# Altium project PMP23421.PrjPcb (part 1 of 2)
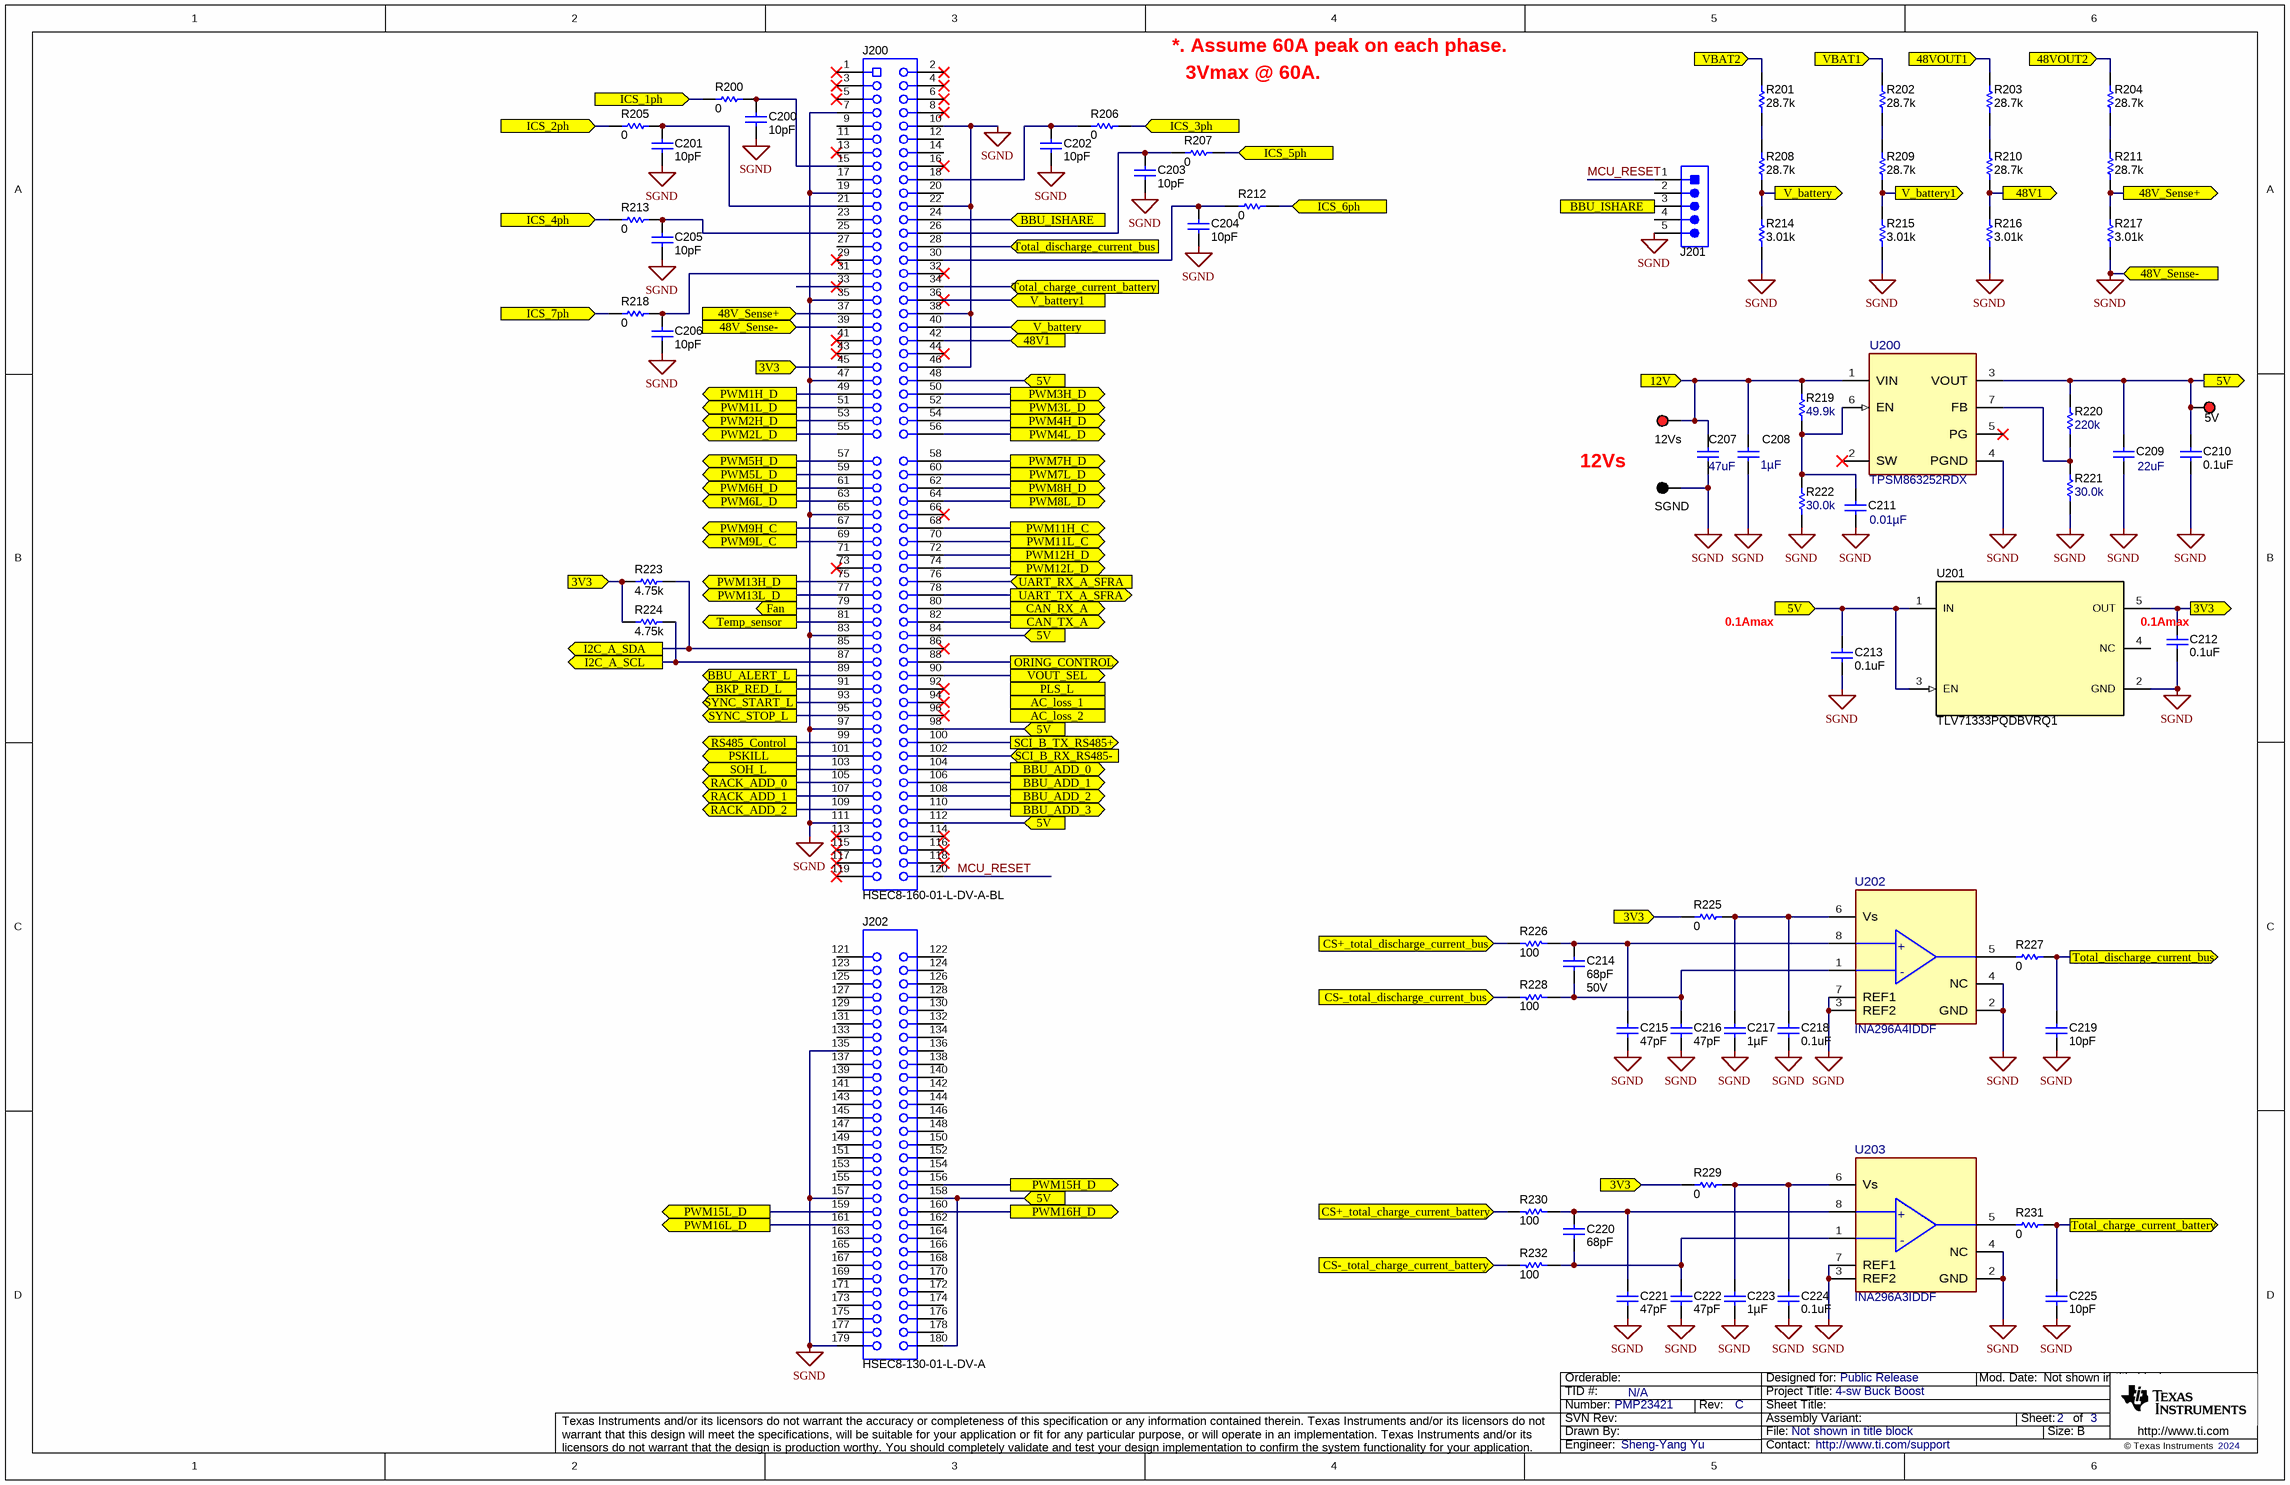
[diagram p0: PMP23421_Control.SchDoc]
CopyrightYear: 2024; PCB_Layout: Sheng-Yang Yu; PCB_Rev: C; PRJ_Customer: Public Release; PRJ_Engineer: Sheng-Yang Yu; PRJ_Number: PMP23421; PRJ_Title: 4-sw Buck Boost; SCH_Rev: C; TechSupport: http://www.ti.com/support; TID: N/A
3 sheets, 215 parts. Net scope: flat (ports and power ports of the same name join across sheets).
Board file: PMP23421.PcbDoc
Sheets:
  PMP23421_Control.SchDoc
  PMP23421_ORING_N_CS.SchDoc
  PMP23421_buffer.SchDoc

## Sheet PMP23421_Control.SchDoc
size 431 x 279 mm; Date: Not shown in title block; ApprovedBy: Not shown in title block; CheckedBy: Not shown in title block; Author: Not shown in title block; CompanyName: Not shown in title block; Engineer: Not shown in title block; Organization: Not shown in title block; Address1: Not shown in title block; Address2: Not shown in title block; Address3: Not shown in title block; Address4: Not shown in title block; DocumentNumber: 2; Revision: Use project parameter SCH_Rev; SheetNumber: 2; SheetTotal: 3; PageSetup: Record=PageOptions¦CenterHorizontal=True¦CenterVertical=True¦PrintScale=1.00¦XCorrection=1.00¦YCorrection=1.00¦PrintKind=0¦BorderSize=5000000¦LeftOffset=0¦BottomOffset=0¦Orientation=2¦PaperLength=1000¦PaperWidth=1000¦Scale=100¦PaperSource=15¦PrintQuality=600¦MediaType=1¦DitherType=10¦PaperKind=Letter¦PrintScaleMode=1

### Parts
5V  5000  [Keystone5000]  (value not drawn)
12Vs  5000  [Keystone5000]  (value not drawn)
C200  ValueDisplayed: 10pF  [0603]  (hidden comment: C0603C100F5GAC7867)
C201  ValueDisplayed: 10pF  [0603]  (hidden comment: C0603C100F5GAC7867)
C202  ValueDisplayed: 10pF  [0603]  (hidden comment: C0603C100F5GAC7867)
C203  ValueDisplayed: 10pF  [0603]  (hidden comment: C0603C100F5GAC7867)
C204  ValueDisplayed: 10pF  [0603]  (hidden comment: C0603C100F5GAC7867)
C205  ValueDisplayed: 10pF  [0603]  (hidden comment: C0603C100F5GAC7867)
C206  ValueDisplayed: 10pF  [0603]  (hidden comment: C0603C100F5GAC7867)
C207  ValueDisplayed: 47uF  [1210_270]  (hidden comment: GRM32ER61C476KE15L)
C208  Cap_F: 1µF  [0805_HV]  (hidden comment: C0805C105K3RACTU)
C209  ValueDisplayed: 22uF  [0805_HV]  (hidden comment: CL21A226KQQNNNE)
C210  ValueDisplayed: 0.1uF  [0402]  (hidden comment: GRM155R70J104KA01D)
C211  ValueDisplayed: 0.01µF  [0402]  (hidden comment: C0402C103K4RACTU)
C212  ValueDisplayed: 0.1uF  [0402]  (hidden comment: GRM155R70J104KA01D)
C213  ValueDisplayed: 0.1uF  [0402]  (hidden comment: GRM155R70J104KA01D)
C214  ValueDisplayed: 68pF  Value2: 50V  [0603]  (hidden comment: 06035A680JAT2A)
C215  ValueDisplayed: 47pF  [0402]  (hidden comment: GRM1555C1H470FA01D)
C216  ValueDisplayed: 47pF  [0402]  (hidden comment: GRM1555C1H470FA01D)
C217  ValueDisplayed: 1µF  [0603]  (hidden comment: C1608X7R1C105K080AC)
C218  ValueDisplayed: 0.1uF  [0402]  (hidden comment: GRM155R70J104KA01D)
C219  ValueDisplayed: 10pF  [0603]  (hidden comment: C0603C100F5GAC7867)
C220  ValueDisplayed: 68pF  [0603]  (hidden comment: 06035A680JAT2A)
C221  ValueDisplayed: 47pF  [0402]  (hidden comment: GRM1555C1H470FA01D)
C222  ValueDisplayed: 47pF  [0402]  (hidden comment: GRM1555C1H470FA01D)
C223  ValueDisplayed: 1µF  [0603]  (hidden comment: C1608X7R1C105K080AC)
C224  ValueDisplayed: 0.1uF  [0402]  (hidden comment: GRM155R70J104KA01D)
C225  ValueDisplayed: 10pF  [0603]  (hidden comment: C0603C100F5GAC7867)
J200  HSEC8-160-01-L-DV-A-BL  [controlCARD-120HSEC]
J201  61300511021  [Wurth_61300511021]  (value not drawn)
J202  HSEC8-130-01-L-DV-A  [controlCARD-180HSEC-60pinAddon]
R200  ValueDisplayed: 0  [0603]  (hidden comment: RC0603JR-070RL)
R201  ValueDisplayed: 28.7k  [0603]  (hidden comment: CRCW060328K7FKEA)
R202  ValueDisplayed: 28.7k  [0603]  (hidden comment: CRCW060328K7FKEA)
R203  ValueDisplayed: 28.7k  [0603]  (hidden comment: CRCW060328K7FKEA)
R204  ValueDisplayed: 28.7k  [0603]  (hidden comment: CRCW060328K7FKEA)
R205  ValueDisplayed: 0  [0603]  (hidden comment: RC0603JR-070RL)
R206  ValueDisplayed: 0  [0603]  (hidden comment: RC0603JR-070RL)
R207  ValueDisplayed: 0  [0603]  (hidden comment: RC0603JR-070RL)
R208  ValueDisplayed: 28.7k  [0603]  (hidden comment: CRCW060328K7FKEA)
R209  ValueDisplayed: 28.7k  [0603]  (hidden comment: CRCW060328K7FKEA)
R210  ValueDisplayed: 28.7k  [0603]  (hidden comment: CRCW060328K7FKEA)
R211  ValueDisplayed: 28.7k  [0603]  (hidden comment: CRCW060328K7FKEA)
R212  ValueDisplayed: 0  [0603]  (hidden comment: RC0603JR-070RL)
R213  ValueDisplayed: 0  [0603]  (hidden comment: RC0603JR-070RL)
R214  ValueDisplayed: 3.01k  [0603]  (hidden comment: CRCW06033K01FKEA)
R215  ValueDisplayed: 3.01k  [0603]  (hidden comment: CRCW06033K01FKEA)
R216  ValueDisplayed: 3.01k  [0603]  (hidden comment: CRCW06033K01FKEA)
R217  ValueDisplayed: 3.01k  [0603]  (hidden comment: CRCW06033K01FKEA)
R218  ValueDisplayed: 0  [0603]  (hidden comment: RC0603JR-070RL)
R219  ValueDisplayed: 49.9k  [0402]  (hidden comment: CRCW040249K9FKED)
R220  ValueDisplayed: 220k  [0402]  (hidden comment: RC0402FR-07220KL)
R221  ValueDisplayed: 30.0k  [0402]  (hidden comment: CRCW040230K0FKED)
R222  ValueDisplayed: 30.0k  [0402]  (hidden comment: CRCW040230K0FKED)
R223  ValueDisplayed: 4.75k  [0603]  (hidden comment: CRCW06034K75FKEA)
R224  ValueDisplayed: 4.75k  [0603]  (hidden comment: CRCW06034K75FKEA)
R225  ValueDisplayed: 0  [0603]  (hidden comment: RC0603JR-070RL)
R226  ValueDisplayed: 100  [0603]  (hidden comment: RC0603FR-07100RL)
R227  ValueDisplayed: 0  [0603]  (hidden comment: RC0603JR-070RL)
R228  ValueDisplayed: 100  [0603]  (hidden comment: RC0603FR-07100RL)
R229  ValueDisplayed: 0  [0603]  (hidden comment: RC0603JR-070RL)
R230  ValueDisplayed: 100  [0603]  (hidden comment: RC0603FR-07100RL)
R231  ValueDisplayed: 0  [0603]  (hidden comment: RC0603JR-070RL)
R232  ValueDisplayed: 100  [0603]  (hidden comment: RC0603FR-07100RL)
SGND  5001  [Keystone5001]  (value not drawn)
U200  TPSM863252RDX  [RDX0007A-MFG]
U201  TLV71333PQDBVRQ1  [DBV0005A_N]
U202  INA296A4IDDF  [DDF0008A-MFG]
U203  INA296A3IDDF  [DDF0008A-MFG]

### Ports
3V3 (in), 3V3 (out), 5V (in), 5V (out), 12V (in), 48V1 (in), 48V1 (out), 48V_Sense+ (in), 48V_Sense+ (out), 48V_Sense- (in), 48VOUT1 (in), 48VOUT2 (in), AC_loss_1 (out), AC_loss_2 (out), BBU_ADD_0 (out), BBU_ADD_1 (out), BBU_ADD_2 (out), BBU_ADD_3 (out), BBU_ALERT_L (out), BBU_ISHARE (in), BKP_RED_L (out), CAN_RX_A (out), CAN_TX_A (out), CS+_total_charge_current_battery (in), CS+_total_discharge_current_bus (in), CS-_total_charge_current_battery (in), CS-_total_discharge_current_bus (in), Fan (out), I2C_A_SCL (out), I2C_A_SDA (out), ICS_1ph (in), ICS_2ph (in), ICS_3ph (in), ICS_4ph (in), ICS_5ph (in), ICS_6ph (in), ICS_7ph (in), ORING_CONTROL (out), PLS_L (out), PSKILL (out), PWM1H_D (out), PWM1L_D (out), PWM2H_D (out), PWM2L_D (out), PWM3H_D (out), PWM3L_D (out), PWM4H_D (out), PWM4L_D (out), PWM5H_D (out), PWM5L_D (out), PWM6H_D (out), PWM6L_D (out), PWM7H_D (out), PWM7L_D (out), PWM8H_D (out), PWM8L_D (out), PWM9H_C (out), PWM9L_C (out), PWM11H_C (out), PWM11L_C (out), PWM12H_D (out), PWM12L_D (out), PWM13H_D (out), PWM13L_D (out), PWM15H_D (out), PWM15L_D (out), PWM16H_D (out), PWM16L_D (out), RACK_ADD_0 (out), RACK_ADD_1 (out), RACK_ADD_2 (out), RS485_Control (out), SCI_B_RX_RS485- (in), SCI_B_TX_RS485+ (out), SOH_L (out), SYNC_START_L (out), SYNC_STOP_L (out), Temp_sensor (out), Total_charge_current_battery (in), Total_charge_current_battery (out), Total_discharge_current_bus (in), Total_discharge_current_bus (out), UART_RX_A_SFRA (in), UART_TX_A_SFRA (out), V_battery1 (in), V_battery1 (out), V_battery (in), V_battery (out), VBAT1 (in), VBAT2 (in), VOUT_SEL (out)

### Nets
SGND: C200.2 C201.2 C202.2 C203.2 C204.2 C205.2 C206.2 C207.2 C208.2 C209.2 C210.2 C211.2 C212.2 C213.2 C215.2 C216.2 C217.2 C218.2 C219.2 C221.2 C222.2 C223.2 C224.2 C225.2 J200.7 J200.10 J200.19 J200.22 J200.35 J200.38 J200.39 J200.46 J200.47 J200.65 J200.83 J200.97 J200.111 J201.5 J202.135 J202.157 J202.179 R214.1 R215.1 R216.1 R217.1 R221.1 R222.1 SGND.1 U200.4(PGND) U201.2(GND) U202.2(GND) U202.3(REF2) U202.4(NC) U202.7(REF1) U203.2(GND) U203.3(REF2) U203.4(NC) U203.7(REF1) ; port 48V_Sense-
3V3: C212.1 J200.45 R223.2 R224.2 R225.1 R229.1 U201.5(OUT) ; port 3V3
5V: 5V.1 C209.1 C210.1 C213.1 J200.48 J200.84 J200.98 J200.112 J202.158 J202.180 R220.2 U200.3(VOUT) U201.1(IN) U201.3(EN) ; port 5V
12V: 12Vs.1 C207.1 C208.1 R219.2 U200.1(VIN) ; port 12V
48V1: J200.42 R210.1 R216.2 ; port 48V1
48V_Sense+: J200.37 R211.1 R217.2 ; port 48V_Sense+
48VOUT1: R203.2 R226.2 ; port 48VOUT1, port CS+_total_discharge_current_bus
48VOUT2: R204.2 ; port 48VOUT2
BBU_ADD_0: J200.104 ; port BBU_ADD_0
BBU_ADD_1: J200.106 ; port BBU_ADD_1
BBU_ADD_2: J200.108 ; port BBU_ADD_2
BBU_ADD_3: J200.110 ; port BBU_ADD_3
BBU_ALERT_L: J200.89 ; port BBU_ALERT_L
BBU_ISHARE: J200.24 J201.3 ; port BBU_ISHARE
BKP_RED_L: J200.91 ; port BKP_RED_L
CAN_RX_A: J200.80 ; port CAN_RX_A
CAN_TX_A: J200.82 ; port CAN_TX_A
CS+_total_charge_current_battery: R202.2 R230.2 ; port VBAT1, port CS+_total_charge_current_battery
CS-_total_charge_current_battery: R201.2 R232.2 ; port VBAT2, port CS-_total_charge_current_battery
CS-_total_discharge_current_bus: R228.2 ; port CS-_total_discharge_current_bus
Fan: J200.79 ; port Fan
I2C_A_SCL: J200.87 R224.1 ; port I2C_A_SCL
I2C_A_SDA: J200.85 R223.1 ; port I2C_A_SDA
ICS_1ph: R200.1 ; port ICS_1ph
ICS_2ph: R205.1 ; port ICS_2ph
ICS_3ph: R206.2 ; port ICS_3ph
ICS_4ph: R213.1 ; port ICS_4ph
ICS_5ph: R207.2 ; port ICS_5ph
ICS_6ph: R212.2 ; port ICS_6ph
ICS_7ph: R218.1 ; port ICS_7ph
MCU_RESET: J200.120 J201.1
ORING_CONTROL: J200.88 ; port ORING_CONTROL
PSKILL: J200.101 ; port PSKILL
PWM1H_D: J200.49 ; port PWM1H_D
PWM1L_D: J200.51 ; port PWM1L_D
PWM2H_D: J200.53 ; port PWM2H_D
PWM2L_D: J200.55 ; port PWM2L_D
PWM3H_D: J200.50 ; port PWM3H_D
PWM3L_D: J200.52 ; port PWM3L_D
PWM4H_D: J200.54 ; port PWM4H_D
PWM4L_D: J200.56 ; port PWM4L_D
PWM5H_D: J200.57 ; port PWM5H_D
PWM5L_D: J200.59 ; port PWM5L_D
PWM6H_D: J200.61 ; port PWM6H_D
PWM6L_D: J200.63 ; port PWM6L_D
PWM7H_D: J200.58 ; port PWM7H_D
PWM7L_D: J200.60 ; port PWM7L_D
PWM8H_D: J200.62 ; port PWM8H_D
PWM8L_D: J200.64 ; port PWM8L_D
PWM9H_C: J200.67 ; port PWM9H_C
PWM9L_C: J200.69 ; port PWM9L_C
PWM11H_C: J200.68 ; port PWM11H_C
PWM11L_C: J200.70 ; port PWM11L_C
PWM12H_D: J200.72 ; port PWM12H_D
PWM12L_D: J200.74 ; port PWM12L_D
PWM13H_D: J200.75 ; port PWM13H_D
PWM13L_D: J200.77 ; port PWM13L_D
PWM15H_D: J202.156 ; port PWM15H_D
PWM15L_D: J202.159 ; port PWM15L_D
PWM16H_D: J202.160 ; port PWM16H_D
PWM16L_D: J202.161 ; port PWM16L_D
RACK_ADD_0: J200.105 ; port RACK_ADD_0
RACK_ADD_1: J200.107 ; port RACK_ADD_1
RACK_ADD_2: J200.109 ; port RACK_ADD_2
RS485_Control: J200.99 ; port RS485_Control
SCI_B_RX_RS485-: J200.102 ; port SCI_B_RX_RS485-
SCI_B_TX_RS485+: J200.100 ; port SCI_B_TX_RS485+
SOH_L: J200.103 ; port SOH_L
SYNC_START_L: J200.93 ; port SYNC_START_L
SYNC_STOP_L: J200.95 ; port SYNC_STOP_L
Temp_sensor: J200.81 ; port Temp_sensor
Total_charge_current_battery: C225.1 J200.34 R231.2 ; port Total_charge_current_battery
Total_discharge_current_bus: C219.1 J200.28 R227.2 ; port Total_discharge_current_bus
UART_RX_A_SFRA: J200.76 ; port UART_RX_A_SFRA
UART_TX_A_SFRA: J200.78 ; port UART_TX_A_SFRA
V_battery: J200.40 R208.1 R214.2 ; port V_battery
V_battery1: J200.36 R209.1 R215.2 ; port V_battery1
VOUT_SEL: J200.90 ; port VOUT_SEL
NetC200_1: C200.1 J200.15 R200.2
NetC201_1: C201.1 J200.21 R205.2
NetC202_1: C202.1 J200.18 R206.1
NetC203_1: C203.1 J200.26 R207.1
NetC204_1: C204.1 J200.30 R212.1
NetC205_1: C205.1 J200.25 R213.2
NetC206_1: C206.1 J200.31 R218.2
NetC211_1: C211.1 R219.1 R222.2 U200.6(EN)
NetC214_1: C214.1 C215.1 R226.1 U202.8(IN+)
NetC214_2: C214.2 C216.1 R228.1 U202.1(IN-)
NetC217_1: C217.1 C218.1 R225.2 U202.6(Vs)
NetC220_1: C220.1 C221.1 R230.1 U203.8(IN+)
NetC220_2: C220.2 C222.1 R232.1 U203.1(IN-)
NetC223_1: C223.1 C224.1 R229.2 U203.6(Vs)
NetR201_1: R201.1 R208.2
NetR202_1: R202.1 R209.2
NetR203_1: R203.1 R210.2
NetR204_1: R204.1 R211.2
NetR220_1: R220.1 R221.2 U200.7(FB)
NetR227_1: R227.1 U202.5(OUT)
NetR231_1: R231.1 U203.5(OUT)

Not connected (* = marked no-connect by the designer): J200 1* 2* 3* 4* 5* 6* 8* 9 11 12 13* 14 16* 17 20 23 27 29* 32* 33* 41* 43* 44* 66* 71 73* 86* 92* 94* 96* 113* 114* 115* 116* 117* 118* 119*; J201 2 4; J202 121 122 123 124 125 126 127 128 129 130 131 132 133 134 136 137 138 139 140 141 142 143 144 145 146 147 148 149 150 151 152 153 154 155 162 163 164 165 166 167 168 169 170 171 172 173 174 175 176 177 178; U200 2(SW)* 5(PG)*; U201 4(NC)

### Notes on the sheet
- *. Assume 60A peak on each phase.
- 3Vmax @ 60A.
- (near SGND) 12Vs
- (near C213) 0.1Amax
- (near C212) 0.1Amax

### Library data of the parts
5V 12Vs = 5000: Test Point, Miniature, Red, TH; Manufacturer: Keystone; CompType: Test Point Loop; ContactFinish: Silver; Green_Lifecycle: Active; Green_REACh: Passed
C200-C206 C219 C225 = C0603C100F5GAC7867: CAP, CERM, 10 pF, 50 V,+/- 1%, C0G/NP0, 0603; Manufacturer: Kemet; Polarized: N; CompType: Capacitor; Value: 10pF; U/M: EA; Cap_F: 0.00000000001; Tolerance_%: 1; VDC_V: 50; Value2: 50V; TaMin_C: -55; TaMax_C: 125; SizeArea_mm2: 1.28; SizeAreaWB_mm2: 4.68; SizeX_mm: 1.6; SizeY_mm: 0.8; AEC Category: Q200; Green_Lifecycle: Active; Green_REACh: Passed
C207 = CMP-0009211-2: CAP, CERM, 47 uF, 16 V, +/- 10%, X5R, 1210; Manufacturer: MuRata; TaMin_C: -55°C; Polarized: N; SizeAreaWB_mm2: 14.7; Value1: Unknown; U/M: EA; Value: 47uF; TaMax_C: 85°C; SizeZ_mm: 2.7; SizeX_mm: 3.2; SizeY_mm: 2.5; Cap_Case: 1210; Value2: 16V; SizeArea_mm2: 8; CompType: Capacitor; Cap_F: 47µF; AEC Category: Q200
C208 = CMP-0007728-2: CAP, CERM, 1 uF, 25 V, +/- 10%, X7R, 0805; Manufacturer: Kemet; TaMin_C: -55°C; Polarized: N; SizeAreaWB_mm2: 6.75; Value1: Unknown; U/M: EA; Value: 1uF; TaMax_C: 125°C; SizeZ_mm: 1.45; SizeX_mm: 2; SizeY_mm: 1.25; Cap_Case: 0805; Value2: 25V; SizeArea_mm2: 2.5; CompType: Capacitor; AEC Category: Q200
C209 = CMP-0007989-2: CAP, CERM, 22 uF, 6.3 V, +/- 10%, X5R, 0805; Manufacturer: Samsung Electro-Mechanics; TaMin_C: -55°C; Polarized: N; SizeAreaWB_mm2: 6.75; Value1: Unknown; U/M: EA; Value: 22uF; TaMax_C: 85°C; SizeZ_mm: 1.45; SizeX_mm: 2; SizeY_mm: 1.25; Cap_Case: 0805; Value2: 6.3V; SizeArea_mm2: 2.5; CompType: Capacitor; Cap_F: 22µF; AEC Category: Q200
C210 C212 C213 C218 C224 = GRM155R70J104KA01D: CAP, CERM, 0.1uF, 6.3V, +/-10%, X7R, 0402; Manufacturer: MuRata; Polarized: N; CompType: Capacitor; U/M: EA; Cap_F: 0.0000001; Tolerance_%: 10; Value1: Unknown; VDC_V: 6.3; TaMin_C: -55; TaMax_C: 125
C211 = CMP-0078218-1: CAP, CERM, 0.01 µF, 16 V,+/- 10%, X7R, 0402; Manufacturer: Kemet; TaMin_C: -55°C; Polarized: N; Green_Lifecycle: Active; SizeAreaWB_mm2: 3; Green_REACh: Passed; U/M: EA; Value: 0.01uF; TaMax_C: 125°C; SizeZ_mm: 0.6; SizeX_mm: 1; SizeY_mm: 0.5; Value2: 16V; CompType: Capacitor; Cap_F: 10nF; AEC Category: Q200
C214 = 06035A680JAT2A: CAP, CERM, 68 pF, 50 V,+/- 5%, C0G/NP0, 0603; Manufacturer: AVX; Polarized: N; CompType: Capacitor; Value: 68pF; U/M: EA; Cap_F: 0.000000000068; Tolerance_%: 5; ESR_ohm: 0.144; Value1: 0.144 ohm; VDC_V: 50; TaMin_C: -55; TaMax_C: 125; SizeArea_mm2: 1.28; SizeAreaWB_mm2: 4.68; SizeX_mm: 1.6; SizeY_mm: 0.8; SizeZ_mm: 1; AEC Category: Q200; Green_Lifecycle: Active; Green_REACh: Passed
C215 C216 C221 C222 = GRM1555C1H470FA01D: CAP, CERM, 47 pF, 50 V,+/- 1%, C0G/NP0, 0402; Manufacturer: MuRata; Polarized: N; CompType: Capacitor; Value: 47pF; U/M: EA; Cap_F: 0.000000000047; Tolerance_%: 1; VDC_V: 50; Value2: 50V; TaMin_C: -55; TaMax_C: 125; SizeArea_mm2: 0.5; SizeAreaWB_mm2: 3; SizeZ_mm: 0.6; AEC Category: Q200; Green_Lifecycle: Active; Green_REACh: Passed
C217 C223 = C1608X7R1C105K080AC: CAP, CERM, 1 µF, 16 V,+/- 10%, X7R, 0603; Manufacturer: TDK; Polarized: N; CompType: Capacitor; Value: 1uF; U/M: EA; Cap_F: 0.000001; Tolerance_%: 10; ESR_ohm: 0.0057; Value1: 0.0057 ohm; VDC_V: 16; Value2: 16V; TaMin_C: -55; TaMax_C: 125; SizeArea_mm2: 1.28; SizeAreaWB_mm2: 4.68; SizeX_mm: 1.6; SizeY_mm: 0.8; SizeZ_mm: 1; AEC Category: Q200; Green_Lifecycle: Active; Green_REACh: Passed
C220 = 06035A680JAT2A: CAP, CERM, 68 pF, 50 V,+/- 5%, C0G/NP0, 0603; Manufacturer: AVX; Polarized: N; CompType: Capacitor; Value: 68pF; U/M: EA; Cap_F: 0.000000000068; Tolerance_%: 5; ESR_ohm: 0.144; Value1: 0.144 ohm; VDC_V: 50; Value2: 50V; TaMin_C: -55; TaMax_C: 125; SizeArea_mm2: 1.28; SizeAreaWB_mm2: 4.68; SizeX_mm: 1.6; SizeY_mm: 0.8; SizeZ_mm: 1; AEC Category: Q200; Green_Lifecycle: Active; Green_REACh: Passed
J200 = CMP-0003814-2: C2000 controlCARD-120HSEC connector, SMT; Manufacturer: Samtec; Note: The pin numbering does not match Samtec datasheet
J201 = CMP-0054800-1: Header, 2.54 mm, 5x1, Gold, R/A, TH; Manufacturer: Wurth Elektronik; CNHeader: TRUE; Shrouded: N; Gender: Male; Row_Count: 1; Pitch_mm: 2.54; CT: FALSE
J202 = CMP-0003859-2: C2000 controlCARD-180HSEC (60-pin addon) connector, SMT; Manufacturer: Samtec; Note: The pin numbering does not match Samtec datasheet
R200 R205-R207 R212 R213 R218 R225 R227 R229 R231 = RC0603JR-070RL: RES, 0, 5%, 0.1 W, 0603; Manufacturer: Yageo America; CompType: Resistor; Value: 0; Value_Code: 0000; Tolerance_%: 5; Power_W: 0.1; Value2: 0.1W; VDC_V: 50; TempCo: 200 ppm/C; SizeArea_mm2: 1.28; SizeX_mm: 1.6; SizeY_mm: 0.8; SizeZ_mm: 1; EIA_Code: E24; U/M: EA; AEC Category: Q200; Green_Lifecycle: Active; Green_REACh: Passed
R201-R204 R208-R211 = CRCW060328K7FKEA: RES, 28.7 k, 1%, 0.1 W, 0603; Manufacturer: Vishay-Dale; CompType: Resistor; Value: 28.7k; Res_ohm: 28700; Value_Code: 28k7; Tolerance_%: 1; Power_W: 0.1; Value2: 0.1W; VDC_V: 75; TempCo: 100 ppm/C; SizeArea_mm2: 1.28; SizeX_mm: 1.6; SizeY_mm: 0.8; EIA_Code: E96; U/M: EA; AEC Category: Q200
R214-R217 = CRCW06033K01FKEA: RES, 3.01 k, 1%, 0.1 W, 0603; Manufacturer: Vishay-Dale; CompType: Resistor; Value: 3.01k; Res_ohm: 3010; Value_Code: 3k01; Tolerance_%: 1; Power_W: 0.1; Value2: 0.1W; VDC_V: 75; TempCo: 100 ppm/C; SizeArea_mm2: 1.28; SizeX_mm: 1.6; SizeY_mm: 0.8; EIA_Code: E96; U/M: EA; AEC Category: Q200; Green_Lifecycle: Active; Green_REACh: Passed
R219 = CMP-0026403-2: RES, 49.9 k, 1%, 0.063 W, AEC-Q200 Grade 0, 0402; Manufacturer: Vishay-Dale; Power_W: 63mW; TempCo: 100 ppm/C; Value_Code: 49k9; Value: 49.9k; EIA_Code: E96; SizeX_mm: 1; SizeY_mm: 0.5; SizeZ_mm: 0.6; Value2: 0.063W; CompType: Resistor; AEC Qualified: Y; VDC_V: 50V; AEC Category: Q200; AEC Grade: 0
R220 = CMP-0026728-1: RES, 220 k, 1%, 0.0625 W, 0402; Manufacturer: Yageo America; Power_W: 62.5mW; TempCo: 100 ppm/C; U/M: EA; Value: 220k; SizeX_mm: 1; SizeY_mm: 0.5; SizeZ_mm: 0.6; CompType: Resistor; AEC Qualified: N; VDC_V: 50V; AEC Category: Q200
R221 R222 = CMP-0078244-2: RES, 30.0 k, 1%, 0.063 W, AEC-Q200 Grade 0, 0402; Manufacturer: Vishay-Dale; Power_W: 63mW; Green_Lifecycle: Active; TempCo: 100 ppm/C; Value_Code: 30k0; Green_REACh: Passed; Value: 30.0k; Res_ohm: 30k; SizeX_mm: 1; SizeY_mm: 0.5; SizeZ_mm: 0.6; Value2: 0.063W; CompType: Resistor; AEC Qualified: Y; VDC_V: 50V; AEC Grade: 0; AEC Category: Q200
R223 R224 = CRCW06034K75FKEA: RES, 4.75 k, 1%, 0.1 W, 0603; Manufacturer: Vishay-Dale; CompType: Resistor; Value: 4.75k; Res_ohm: 4750; Value_Code: 4k75; Tolerance_%: 1; Power_W: 0.1; Value2: 0.1W; VDC_V: 75; TempCo: 100 ppm/C; SizeArea_mm2: 1.28; SizeX_mm: 1.6; SizeY_mm: 0.8; EIA_Code: E96; U/M: EA; AEC Category: Q200; Green_Lifecycle: Active; Green_REACh: Passed
R226 R228 R230 R232 = RC0603FR-07100RL: RES, 100, 1%, 0.1 W, 0603; Manufacturer: Yageo America; CompType: Resistor; Value: 100; Value_Code: 100R; Tolerance_%: 1; Power_W: 0.1; Value2: 0.1W; VDC_V: 150; TempCo: 200 ppm/C; SizeArea_mm2: 1.28; SizeX_mm: 1.6; SizeY_mm: 0.8; EIA_Code: E96; U/M: EA; AEC Category: Q200; Green_Lifecycle: Active; Green_REACh: Passed
SGND = 5001: Test Point, Miniature, Black, TH; Manufacturer: Keystone; CompType: Test Point Loop; ContactFinish: Silver; Green_Lifecycle: Active; Green_REACh: Passed
U200 = CMP-0097277-2: 3-V to 17-V Input, 3-A Synchronous Buck Module, QFN-FCMOD7; Manufacturer: Texas Instruments; Nominal Supply Current: 100-400uA; SizeZ_mm: 2.1mm; AEC Qualified: No; Output Type: AdjustableProgrammable; AEC Grade: NA; Standoff Height: 0mm; Max Supply Voltage: 17V; Min Supply Voltage: 3V; Number Of Outputs: 1; Switching Frequency: 1200/2000kHz; TJmax_C: +125°C; Max Duty Cycle: 95; Output Voltage: 0.6-10V; AEC Category: Q200; CompType: IC
U201 = TLV71333PQDBVRQ1: Capacitor-Free, 150-mA, Low-Dropout Regulator with Foldback Current Limit for Portable Devices, DBV0005A; Manufacturer: Texas Instruments; SymbolCreator: Altium; SizeArea_mm2: 8.12; SizeAreaWB_mm2: 14.82; SizeX_mm: 2.8; SizeY_mm: 2.9; SizeZ_mm: 1.45; CompType: IC; U/M: EA
U202 = CMP-0093655-2: -4-V to 110-V, Bidirectional, 1-MHz, 5V/μs, Ultra-Precise Current Sense Amplifier, SOT23-8; Manufacturer: Texas Instruments; CompType: IC; Number Of Channels: 1; Nominal Supply Current: 2.5mA; Input Bias Current: 40uA; Max Supply Voltage: 20V; Voltage Gain: 0.1V/mV; TJmax_C: +150°C; TaMax_C: +125°C; TaMin_C: -40°C; Standoff Height: 0mm; Input Offset Voltage: 0.002mV; AEC Qualified: No; Bandwidth: 1MHz; AEC Category: Q200; Response Time: 1.5us; Min Supply Voltage: 2.7V; SizeZ_mm: 1.1mm
U203 = CMP-0093654-2: -4-V to 110-V, Bidirectional, 1-MHz, 5V/μs, Ultra-Precise Current Sense Amplifier, SOT23-8; Manufacturer: Texas Instruments; Voltage Gain: 0.05V/mV; SizeZ_mm: 1.1mm; Nominal Supply Current: 2.5mA; AEC Category: Q200; Bandwidth: 1MHz; Standoff Height: 0mm; TaMin_C: -40°C; Input Bias Current: 40uA; TaMax_C: +125°C; Min Supply Voltage: 2.7V; Input Offset Voltage: 0.002mV; Number Of Channels: 1; AEC Qualified: No; CompType: IC; Response Time: 1.5us; Max Supply Voltage: 20V; TJmax_C: +150°C

## Sheet PMP23421_ORING_N_CS.SchDoc
size 431 x 279 mm; Date: Not shown in title block; ApprovedBy: Not shown in title block; CheckedBy: Not shown in title block; Author: Not shown in title block; CompanyName: Not shown in title block; Engineer: Not shown in title block; Organization: Not shown in title block; Address1: Not shown in title block; Address2: Not shown in title block; Address3: Not shown in title block; Address4: Not shown in title block; DocumentNumber: 1; Revision: Use project parameter SCH_Rev; SheetNumber: 1; SheetTotal: 3; PageSetup: Record=PageOptions¦CenterHorizontal=True¦CenterVertical=True¦PrintScale=1.00¦XCorrection=1.00¦YCorrection=1.00¦PrintKind=0¦BorderSize=5000000¦LeftOffset=0¦BottomOffset=0¦Orientation=2¦PaperLength=1000¦PaperWidth=1000¦Scale=100¦PaperSource=15¦PrintQuality=600¦MediaType=1¦DitherType=10¦PaperKind=Letter¦PrintScaleMode=1
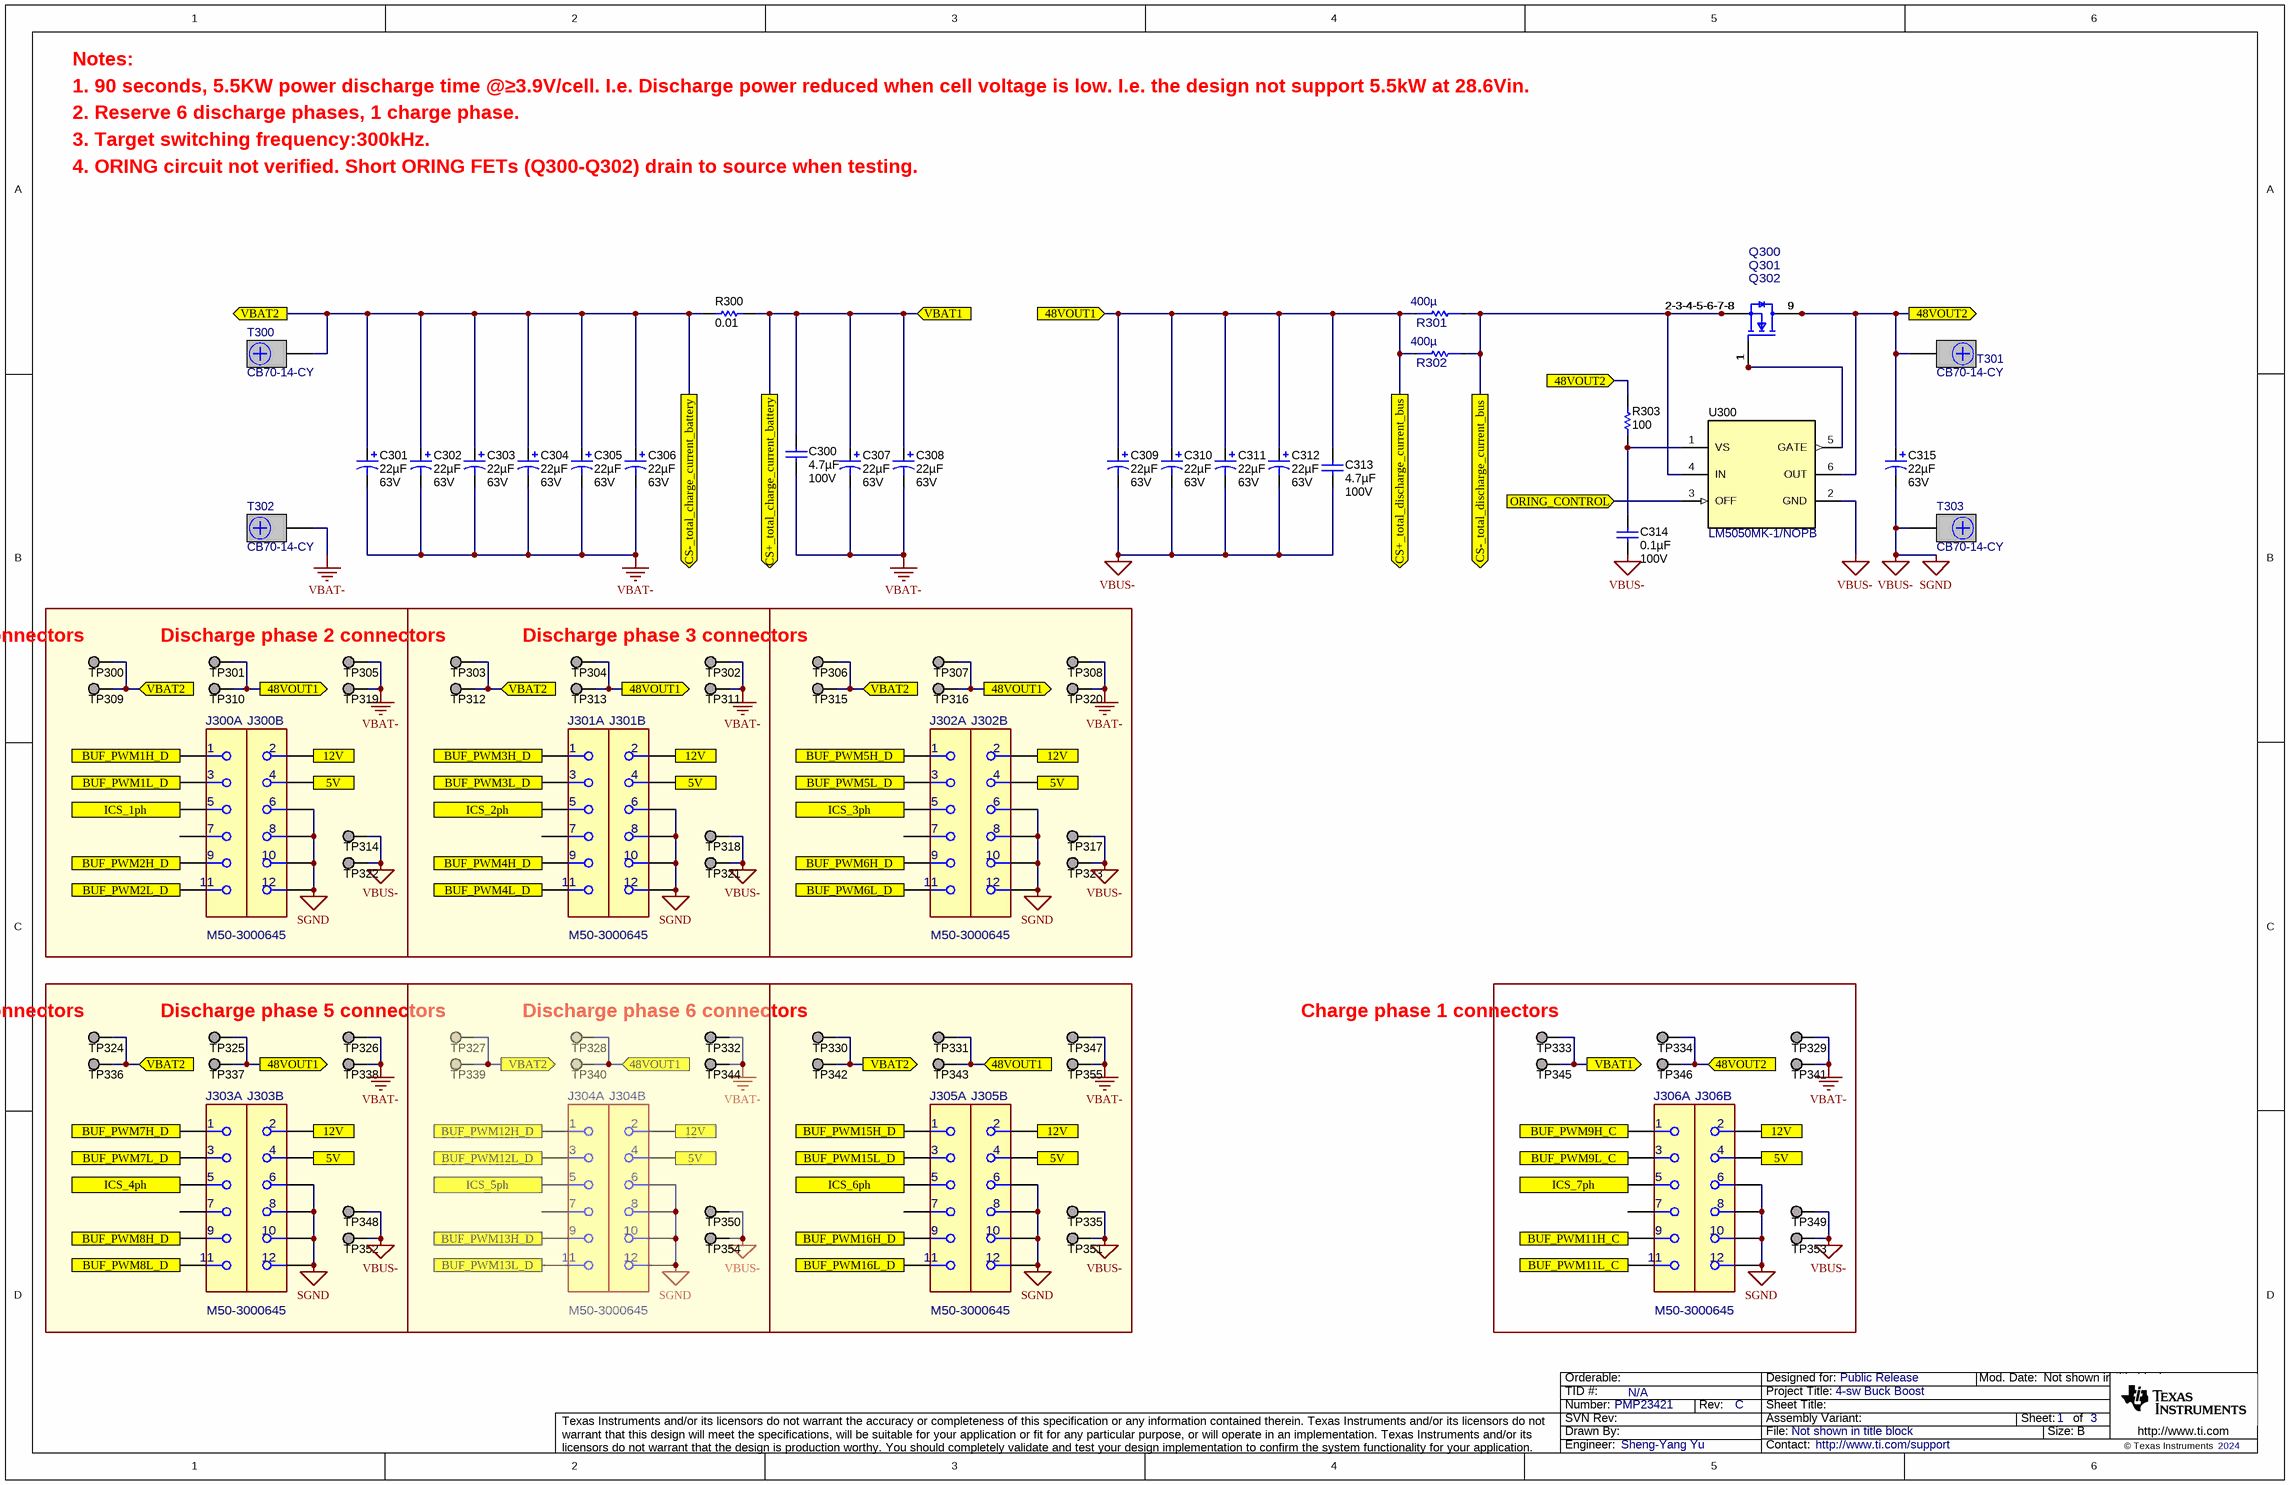
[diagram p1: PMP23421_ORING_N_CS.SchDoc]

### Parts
C300  ValueDisplayed: 4.7µF  Value2: 100V  [1206_180]  (hidden comment: GRJ31CC72A475KE01L)
C301  ValueDisplayed: 22µF  Value2: 63V  [SM_RADIAL_D]  (hidden comment: 63PFV22M6.3X8)
C302  ValueDisplayed: 22µF  Value2: 63V  [SM_RADIAL_D]  (hidden comment: 63PFV22M6.3X8)
C303  ValueDisplayed: 22µF  Value2: 63V  [SM_RADIAL_D]  (hidden comment: 63PFV22M6.3X8)
C304  ValueDisplayed: 22µF  Value2: 63V  [SM_RADIAL_D]  (hidden comment: 63PFV22M6.3X8)
C305  ValueDisplayed: 22µF  Value2: 63V  [SM_RADIAL_D]  (hidden comment: 63PFV22M6.3X8)
C306  ValueDisplayed: 22µF  Value2: 63V  [SM_RADIAL_D]  (hidden comment: 63PFV22M6.3X8)
C307  ValueDisplayed: 22µF  Value2: 63V  [SM_RADIAL_D]  (hidden comment: 63PFV22M6.3X8)
C308  ValueDisplayed: 22µF  Value2: 63V  [SM_RADIAL_D]  (hidden comment: 63PFV22M6.3X8)
C309  ValueDisplayed: 22µF  Value2: 63V  [SM_RADIAL_D]  (hidden comment: 63PFV22M6.3X8)
C310  ValueDisplayed: 22µF  Value2: 63V  [SM_RADIAL_D]  (hidden comment: 63PFV22M6.3X8)
C311  ValueDisplayed: 22µF  Value2: 63V  [SM_RADIAL_D]  (hidden comment: 63PFV22M6.3X8)
C312  ValueDisplayed: 22µF  Value2: 63V  [SM_RADIAL_D]  (hidden comment: 63PFV22M6.3X8)
C313  ValueDisplayed: 4.7µF  Value2: 100V  [1206_180]  (hidden comment: GRJ31CC72A475KE01L)
C314  ValueDisplayed: 0.1µF  Value2: 100V  [1206]  (hidden comment: 12061C104JAT2A)
C315  ValueDisplayed: 22µF  Value2: 63V  [SM_RADIAL_D]  (hidden comment: 63PFV22M6.3X8)
J300  M50-3000645  [FP-M50-3000645_HDR12-MFG]  (parts A,B of 2)
J301  M50-3000645  [FP-M50-3000645_HDR12-MFG]  (parts A,B of 2)
J302  M50-3000645  [FP-M50-3000645_HDR12-MFG]  (parts A,B of 2)
J303  M50-3000645  [FP-M50-3000645_HDR12-MFG]  (parts A,B of 2)
J304  M50-3000645  [FP-M50-3000645_HDR12-MFG]  (parts A,B of 2)
J305  M50-3000645  [FP-M50-3000645_HDR12-MFG]  (parts A,B of 2)
J306  M50-3000645  [FP-M50-3000645_HDR12-MFG]  (parts A,B of 2)
Q300  IPT010N08NM5ATMA1  [FP-IPT010N08NM5ATMA1_HSOF8-MFG]  (value not drawn)
Q301  IPT010N08NM5ATMA1  [FP-IPT010N08NM5ATMA1_HSOF8-MFG]  (value not drawn)
Q302  IPT010N08NM5ATMA1  [FP-IPT010N08NM5ATMA1_HSOF8-MFG]  (value not drawn)
R300  ValueDisplayed: 0.01  [2512]  (hidden comment: CSR2512C0R01F)
R301  value 400µ  [FP-PU3921FKNP90U4L_3921-MFG]  (hidden comment: PU3921FKNP90U4L)
R302  value 400µ  [FP-PU3921FKNP90U4L_3921-MFG]  (hidden comment: PU3921FKNP90U4L)
R303  ValueDisplayed: 100  [0805_HV]  (hidden comment: CRCW0805100RDHEAP)
T300  CB70-14-CY  [CB70-14-CY]
T301  CB70-14-CY  [CB70-14-CY]
T302  CB70-14-CY  [CB70-14-CY]
T303  CB70-14-CY  [CB70-14-CY]
TP300  Suggest using a net name here  [Mill-Max_0312-0-15-15-34-27-10-0]  (value not drawn)
TP301  Suggest using a net name here  [Mill-Max_0312-0-15-15-34-27-10-0]  (value not drawn)
TP302  Suggest using a net name here  [Mill-Max_0312-0-15-15-34-27-10-0]  (value not drawn)
TP303  Suggest using a net name here  [Mill-Max_0312-0-15-15-34-27-10-0]  (value not drawn)
TP304  Suggest using a net name here  [Mill-Max_0312-0-15-15-34-27-10-0]  (value not drawn)
TP305  Suggest using a net name here  [Mill-Max_0312-0-15-15-34-27-10-0]  (value not drawn)
TP306  Suggest using a net name here  [Mill-Max_0312-0-15-15-34-27-10-0]  (value not drawn)
TP307  Suggest using a net name here  [Mill-Max_0312-0-15-15-34-27-10-0]  (value not drawn)
TP308  Suggest using a net name here  [Mill-Max_0312-0-15-15-34-27-10-0]  (value not drawn)
TP309  Suggest using a net name here  [Mill-Max_0312-0-15-15-34-27-10-0]  (value not drawn)
TP310  Suggest using a net name here  [Mill-Max_0312-0-15-15-34-27-10-0]  (value not drawn)
TP311  Suggest using a net name here  [Mill-Max_0312-0-15-15-34-27-10-0]  (value not drawn)
TP312  Suggest using a net name here  [Mill-Max_0312-0-15-15-34-27-10-0]  (value not drawn)
TP313  Suggest using a net name here  [Mill-Max_0312-0-15-15-34-27-10-0]  (value not drawn)
TP314  Suggest using a net name here  [Mill-Max_0312-0-15-15-34-27-10-0]  (value not drawn)
TP315  Suggest using a net name here  [Mill-Max_0312-0-15-15-34-27-10-0]  (value not drawn)
TP316  Suggest using a net name here  [Mill-Max_0312-0-15-15-34-27-10-0]  (value not drawn)
TP317  Suggest using a net name here  [Mill-Max_0312-0-15-15-34-27-10-0]  (value not drawn)
TP318  Suggest using a net name here  [Mill-Max_0312-0-15-15-34-27-10-0]  (value not drawn)
TP319  Suggest using a net name here  [Mill-Max_0312-0-15-15-34-27-10-0]  (value not drawn)
TP320  Suggest using a net name here  [Mill-Max_0312-0-15-15-34-27-10-0]  (value not drawn)
TP321  Suggest using a net name here  [Mill-Max_0312-0-15-15-34-27-10-0]  (value not drawn)
TP322  Suggest using a net name here  [Mill-Max_0312-0-15-15-34-27-10-0]  (value not drawn)
TP323  Suggest using a net name here  [Mill-Max_0312-0-15-15-34-27-10-0]  (value not drawn)
TP324  Suggest using a net name here  [Mill-Max_0312-0-15-15-34-27-10-0]  (value not drawn)
TP325  Suggest using a net name here  [Mill-Max_0312-0-15-15-34-27-10-0]  (value not drawn)
TP326  Suggest using a net name here  [Mill-Max_0312-0-15-15-34-27-10-0]  (value not drawn)
TP327  Suggest using a net name here  [Mill-Max_0312-0-15-15-34-27-10-0]  (value not drawn)
TP328  Suggest using a net name here  [Mill-Max_0312-0-15-15-34-27-10-0]  (value not drawn)
TP329  Suggest using a net name here  [Mill-Max_0312-0-15-15-34-27-10-0]  (value not drawn)
TP330  Suggest using a net name here  [Mill-Max_0312-0-15-15-34-27-10-0]  (value not drawn)
TP331  Suggest using a net name here  [Mill-Max_0312-0-15-15-34-27-10-0]  (value not drawn)
TP332  Suggest using a net name here  [Mill-Max_0312-0-15-15-34-27-10-0]  (value not drawn)
TP333  Suggest using a net name here  [Mill-Max_0312-0-15-15-34-27-10-0]  (value not drawn)
TP334  Suggest using a net name here  [Mill-Max_0312-0-15-15-34-27-10-0]  (value not drawn)
TP335  Suggest using a net name here  [Mill-Max_0312-0-15-15-34-27-10-0]  (value not drawn)
TP336  Suggest using a net name here  [Mill-Max_0312-0-15-15-34-27-10-0]  (value not drawn)
TP337  Suggest using a net name here  [Mill-Max_0312-0-15-15-34-27-10-0]  (value not drawn)
TP338  Suggest using a net name here  [Mill-Max_0312-0-15-15-34-27-10-0]  (value not drawn)
TP339  Suggest using a net name here  [Mill-Max_0312-0-15-15-34-27-10-0]  (value not drawn)
TP340  Suggest using a net name here  [Mill-Max_0312-0-15-15-34-27-10-0]  (value not drawn)
TP341  Suggest using a net name here  [Mill-Max_0312-0-15-15-34-27-10-0]  (value not drawn)
TP342  Suggest using a net name here  [Mill-Max_0312-0-15-15-34-27-10-0]  (value not drawn)
TP343  Suggest using a net name here  [Mill-Max_0312-0-15-15-34-27-10-0]  (value not drawn)
TP344  Suggest using a net name here  [Mill-Max_0312-0-15-15-34-27-10-0]  (value not drawn)
TP345  Suggest using a net name here  [Mill-Max_0312-0-15-15-34-27-10-0]  (value not drawn)
TP346  Suggest using a net name here  [Mill-Max_0312-0-15-15-34-27-10-0]  (value not drawn)
TP347  Suggest using a net name here  [Mill-Max_0312-0-15-15-34-27-10-0]  (value not drawn)
TP348  Suggest using a net name here  [Mill-Max_0312-0-15-15-34-27-10-0]  (value not drawn)
TP349  Suggest using a net name here  [Mill-Max_0312-0-15-15-34-27-10-0]  (value not drawn)
TP350  Suggest using a net name here  [Mill-Max_0312-0-15-15-34-27-10-0]  (value not drawn)
TP351  Suggest using a net name here  [Mill-Max_0312-0-15-15-34-27-10-0]  (value not drawn)
TP352  Suggest using a net name here  [Mill-Max_0312-0-15-15-34-27-10-0]  (value not drawn)
TP353  Suggest using a net name here  [Mill-Max_0312-0-15-15-34-27-10-0]  (value not drawn)
TP354  Suggest using a net name here  [Mill-Max_0312-0-15-15-34-27-10-0]  (value not drawn)
TP355  Suggest using a net name here  [Mill-Max_0312-0-15-15-34-27-10-0]  (value not drawn)
U300  LM5050MK-1/NOPB  [DDC0006A_N]

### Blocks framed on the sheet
Discharge phase 1 connectors: J300 TP300 TP301 TP305 TP309 TP310 TP314 TP319 TP322
Discharge phase 2 connectors: J301 TP302-TP304 TP311-TP313 TP318 TP321
Discharge phase 3 connectors: J302 TP306-TP308 TP315-TP317 TP320 TP323
Discharge phase 4 connectors: J303 TP324-TP326 TP336-TP338 TP348 TP352
Discharge phase 5 connectors: J304 TP327 TP328 TP332 TP339 TP340 TP344 TP350 TP354
Discharge phase 6 connectors: J305 TP330 TP331 TP335 TP342 TP343 TP347 TP351 TP355
Charge phase 1 connectors: J306 TP329 TP333 TP334 TP341 TP345 TP346 TP349 TP353

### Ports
5V (in), 12V (in), 48VOUT1 (in), 48VOUT1 (out), 48VOUT2 (in), 48VOUT2 (out), BUF_PWM1H_D (in), BUF_PWM1L_D (in), BUF_PWM2H_D (in), BUF_PWM2L_D (in), BUF_PWM3H_D (in), BUF_PWM3L_D (in), BUF_PWM4H_D (in), BUF_PWM4L_D (in), BUF_PWM5H_D (in), BUF_PWM5L_D (in), BUF_PWM6H_D (in), BUF_PWM6L_D (in), BUF_PWM7H_D (in), BUF_PWM7L_D (in), BUF_PWM8H_D (in), BUF_PWM8L_D (in), BUF_PWM9H_C (in), BUF_PWM9L_C (in), BUF_PWM11H_C (in), BUF_PWM11L_C (in), BUF_PWM12H_D (in), BUF_PWM12L_D (in), BUF_PWM13H_D (in), BUF_PWM13L_D (in), BUF_PWM15H_D (in), BUF_PWM15L_D (in), BUF_PWM16H_D (in), BUF_PWM16L_D (in), CS+_total_charge_current_battery (out), CS+_total_discharge_current_bus (out), CS-_total_charge_current_battery (out), CS-_total_discharge_current_bus (out), ICS_1ph (in), ICS_2ph (in), ICS_3ph (in), ICS_4ph (in), ICS_5ph (in), ICS_6ph (in), ICS_7ph (in), ORING_CONTROL (in), VBAT1 (in), VBAT1 (out), VBAT2 (in), VBAT2 (out)

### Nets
SGND: C309.2(-) C310.2(-) C311.2(-) C312.2(-) C313.2 C314.2 C315.2(-) J300.6 J300.8 J300.10 J300.12 J301.6 J301.8 J301.10 J301.12 J302.6 J302.8 J302.10 J302.12 J303.6 J303.8 J303.10 J303.12 J304.6 J304.8 J304.10 J304.12 J305.6 J305.8 J305.10 J305.12 J306.6 J306.8 J306.10 J306.12 T303.1 TP314.1 TP317.1 TP318.1 TP321.1 TP322.1 TP323.1 TP335.1 TP348.1 TP349.1 TP350.1 TP351.1 TP352.1 TP353.1 TP354.1 U300.2(GND)  [also labelled VBUS-]
VBAT-: C300.2 C301.2(-) C302.2(-) C303.2(-) C304.2(-) C305.2(-) C306.2(-) C307.2(-) C308.2(-) T302.1 TP302.1 TP305.1 TP308.1 TP311.1 TP319.1 TP320.1 TP326.1 TP329.1 TP332.1 TP338.1 TP341.1 TP344.1 TP347.1 TP355.1
5V: J300.4 J301.4 J302.4 J303.4 J304.4 J305.4 J306.4 ; port 5V
12V: J300.2 J301.2 J302.2 J303.2 J304.2 J305.2 J306.2 ; port 12V
48VOUT1: C309.1(+) C310.1(+) C311.1(+) C312.1(+) C313.1 R301.1 R302.1 TP301.1 TP304.1 TP307.1 TP310.1 TP313.1 TP316.1 TP325.1 TP328.1 TP331.1 TP337.1 TP340.1 TP343.1 ; port 48VOUT1, port CS+_total_discharge_current_bus
48VOUT2: C315.1(+) Q300.9(Drain) Q301.9(Drain) Q302.9(Drain) R303.2 T301.1 TP334.1 TP346.1 U300.6(OUT) ; port 48VOUT2
BUF_PWM1H_D: J300.1 ; port BUF_PWM1H_D
BUF_PWM1L_D: J300.3 ; port BUF_PWM1L_D
BUF_PWM2H_D: J300.9 ; port BUF_PWM2H_D
BUF_PWM2L_D: J300.11 ; port BUF_PWM2L_D
BUF_PWM3H_D: J301.1 ; port BUF_PWM3H_D
BUF_PWM3L_D: J301.3 ; port BUF_PWM3L_D
BUF_PWM4H_D: J301.9 ; port BUF_PWM4H_D
BUF_PWM4L_D: J301.11 ; port BUF_PWM4L_D
BUF_PWM5H_D: J302.1 ; port BUF_PWM5H_D
BUF_PWM5L_D: J302.3 ; port BUF_PWM5L_D
BUF_PWM6H_D: J302.9 ; port BUF_PWM6H_D
BUF_PWM6L_D: J302.11 ; port BUF_PWM6L_D
BUF_PWM7H_D: J303.1 ; port BUF_PWM7H_D
BUF_PWM7L_D: J303.3 ; port BUF_PWM7L_D
BUF_PWM8H_D: J303.9 ; port BUF_PWM8H_D
BUF_PWM8L_D: J303.11 ; port BUF_PWM8L_D
BUF_PWM9H_C: J306.1 ; port BUF_PWM9H_C
BUF_PWM9L_C: J306.3 ; port BUF_PWM9L_C
BUF_PWM11H_C: J306.9 ; port BUF_PWM11H_C
BUF_PWM11L_C: J306.11 ; port BUF_PWM11L_C
BUF_PWM12H_D: J304.1 ; port BUF_PWM12H_D
BUF_PWM12L_D: J304.3 ; port BUF_PWM12L_D
BUF_PWM13H_D: J304.9 ; port BUF_PWM13H_D
BUF_PWM13L_D: J304.11 ; port BUF_PWM13L_D
BUF_PWM15H_D: J305.1 ; port BUF_PWM15H_D
BUF_PWM15L_D: J305.3 ; port BUF_PWM15L_D
BUF_PWM16H_D: J305.9 ; port BUF_PWM16H_D
BUF_PWM16L_D: J305.11 ; port BUF_PWM16L_D
CS+_total_charge_current_battery: C300.1 C307.1(+) C308.1(+) R300.2 TP333.1 TP345.1 ; port VBAT1, port CS+_total_charge_current_battery
CS-_total_charge_current_battery: C301.1(+) C302.1(+) C303.1(+) C304.1(+) C305.1(+) C306.1(+) R300.1 T300.1 TP300.1 TP303.1 TP306.1 TP309.1 TP312.1 TP315.1 TP324.1 TP327.1 TP330.1 TP336.1 TP339.1 TP342.1 ; port VBAT2, port CS-_total_charge_current_battery
CS-_total_discharge_current_bus: Q300.2-3-4-5-6-7-8(Source) Q301.2-3-4-5-6-7-8(Source) Q302.2-3-4-5-6-7-8(Source) R301.2 R302.2 U300.4(IN) ; port CS-_total_discharge_current_bus
ICS_1ph: J300.5 ; port ICS_1ph
ICS_2ph: J301.5 ; port ICS_2ph
ICS_3ph: J302.5 ; port ICS_3ph
ICS_4ph: J303.5 ; port ICS_4ph
ICS_5ph: J304.5 ; port ICS_5ph
ICS_6ph: J305.5 ; port ICS_6ph
ICS_7ph: J306.5 ; port ICS_7ph
ORING_CONTROL: U300.3(OFF) ; port ORING_CONTROL
NetC314_1: C314.1 R303.1 U300.1(VS)
NetQ300_1: Q300.1(Gate) Q301.1(Gate) Q302.1(Gate) U300.5(GATE)

Not connected (* = marked no-connect by the designer): J300 7; J301 7; J302 7; J303 7; J304 7; J305 7; J306 7

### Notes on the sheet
- Notes:
- 1. 90 seconds, 5.5KW power discharge time @≥3.9V/cell. I.e. Discharge power reduced when cell voltage is low. I.e. the design not support 5.5kW at 28.6Vin.
- 2. Reserve 6 discharge phases, 1 charge phase.
- 3. Target switching frequency:300kHz.
- 4. ORING circuit not verified. Short ORING FETs (Q300-Q302) drain to source when testing.

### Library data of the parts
C300 C313 = C3216X6S1H475K160AB: CAP CER 4.7UF 100V X7S 1206; Polarized: N; CompType: Capacitor; U/M: EA; Cap_F: 0.0000047; Tolerance_%: 10; VDC_V: 100; TaMin_C: -55; TaMax_C: 105; Cap_Case: 1206; SizeArea_mm2: 5.12; SizeAreaWB_mm2: 10.92; SizeX_mm: 3.2; SizeY_mm: 1.6; SizeZ_mm: 1.8; AEC Category: Q200
C301-C312 C315 = EEE-FK1H220P: CAP ALUM POLY HYB 22UF 63V SMD; Manufacturer: Rubycon; Polarized: Y; CompType: Capacitor; Cap_F: 0.000022; Tolerance_%: 20; Value1: 0.88 ohm; VDC_V: 63; Cap_Case: D; SizeAreaWB_mm2: 84.28; SizeArea_mm2: 51.48; SizeX_mm: 7.8; SizeY_mm: 6.6; SizeZ_mm: 5.4; Green_Lifecycle: Active; Green_REACh: Passed
C314 = 12061C104JAT2A: CAP, CERM, 0.1 µF, 100 V,+/- 5%, X7R, 1206; Manufacturer: AVX; Polarized: N; CompType: Capacitor; Value: 0.1uF; U/M: EA; Cap_F: 0.0000001; Tolerance_%: 5; ESR_ohm: 0.037; Value1: 0.037 ohm; VDC_V: 100; TaMin_C: -55; TaMax_C: 125; SizeArea_mm2: 5.12; SizeAreaWB_mm2: 10.92; SizeX_mm: 3.2; SizeY_mm: 1.6; SizeZ_mm: 1.35; AEC Category: Q200; Green_Lifecycle: Active; Green_REACh: Passed
J300-J306 = CMP-0094055-1: 12 Position Receptacle Connector 0.050" (1.27mm) Through Hole Gold; Manufacturer: Harwin; AEC Qualified: No; Is Female: yes; ContactFinish: Gold,Nickel; SizeZ_mm: 4.55mm; Current_A: 1A; Conn Gender: Female; Conn Orientation: Vertical; Row_Count: 2
Q300-Q302 = CMP-0120006-1: Transistor Power MOSFET N-Channel 80V 425A 8-Pin HSOF T/R; Manufacturer: Infineon; AEC Qualified: No; IdsMax_A: 43A; QgTyp_nC: 178nC @ 10V; Rdson45_ohm: 960µ; SizeZ_mm: 2.4mm; VdsMax_V: 1V; Vgs_V: 20V; ChMode: False; Input Capacitace At Vds: 12000pF @ 40V; Number Of Channels: 1; Power_W: 3.8W; Pulse Drain Current: 1700A; Reverse Recovery Charge: 318nC; Reverse Recovery Time: 106ns; Rthja Max: 62°C/W; Threshold Vgs Max: 3.8V; Threshold Vgs Min: 2.2V; TJmax_C: +175°C; Transconductance: 270S; Turn Off Delay Time: 82ns; Turn On Delay Time: 35ns; Typ Forward Diode Voltage: 0.87V
R300 = CSR2512C0R01F: RES, 0.01, 1%, 3 W, AEC-Q200 Grade 0, 2512; Manufacturer: Riedon; CompType: Resistor; Value: 0.01; Value_Code: R010; Tolerance_%: 1; Power_W: 3; Value2: 3W; TempCo: 75 ppm/C; SizeArea_mm2: 20.16; SizeX_mm: 6.3; SizeY_mm: 3.2; SizeZ_mm: 0.71; EIA_Code: E96; U/M: EA; AEC Category: Q200; AEC Qualified: Y; AEC Grade: 0; Green_Lifecycle: Active; Green_REACh: Passed
R301 R302 = CMP-0096319-1: 400 µOhms ±1% 9W Chip Resistor Nonstandard Automotive AEC-Q200, Current Sense, Moisture Resistant Metal Element; Manufacturer: YAGEO; AEC Qualified: Yes; TempCo: 175ppm/°C; SizeZ_mm: 1.81mm; AEC Grade: Grade 0; Standoff Height: 0.37mm
R303 = CRCW0805100RDHEAP: RES, 100, 0.5%, 0.125 W, AEC-Q200 Grade 0, 0805; Manufacturer: Vishay-Dale; CompType: Resistor; Value: 100; Value_Code: 100R; Tolerance_%: 0.5; Power_W: 0.125; Value2: 0.125W; TempCo: 50 ppm/C; SizeArea_mm2: 2.5; SizeX_mm: 2; SizeY_mm: 1.25; SizeZ_mm: 1.45; EIA_Code: E192; U/M: EA; AEC Category: Q200; AEC Qualified: Y; AEC Grade: 0
T300-T303 = CMP-0055443-2: Terminal 90A Lug; Manufacturer: Panduit; Green_Lifecycle: Not Set; Cert_CULUS: Y; Green_REACh: Incomplete; Voltage_V: 600V; CompType: Screw Terminal; ContactFinish: Copper
TP300-TP355 = 0312-0-15-15-34-27-10-0: Pin Receptacle, .032-.046" .075" Dia, Gold, TH; Manufacturer: Mill-Max; Gender: Female
U300 = CMP-0066129-2: High Side OR-ing FET Controller, DDC0006A (SOT-23-T-6); Manufacturer: Texas Instruments; SizeZ_mm: 0.87; SizeX_mm: 1.65; SizeY_mm: 2.95; SizeArea_mm2: 4.8675; CompType: IC; U/M: EA; SizeAreaWB_mm2: 10.4675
